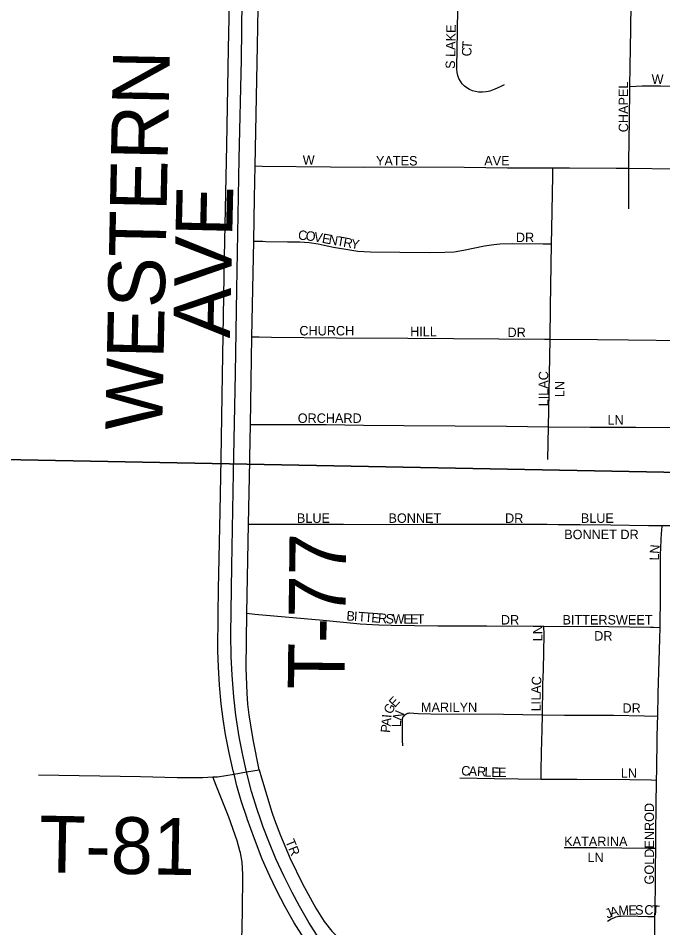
# Model space of a CAD drawing. Extents: x 0 to 68, y 0 to 52.9.
# Drawn here: x 42.193 to 43.045, y 38.666 to 39.867 of the extents above; entities that cross this region are included whole.
import ezdxf

# ---------------------------------------------------------------- set-up
doc = ezdxf.new("R2010")
doc.units = 0
for name, color, linetype in [('Default', 7, 'Continuous'), ('GM_X_Township_Road', 7, 'Continuous'), ('GM_X_Township_Road_Text', 7, 'Continuous'), ('GM_X_Township_Subdivision', 7, 'Continuous'), ('GM_X_Township_Subdivision_Text', 7, 'Continuous')]:
    doc.layers.add(name, color=color, linetype=linetype)

msp = doc.modelspace()

# ---------------------------------------------------------------- linework, layer by layer
at = {"layer": 'Default'}
for points in [[(43.183, 40.6024), (43.1833, 40.5874), (43.1609, 39.2654), (41.829, 39.2909), (41.8559, 40.6193)], [(41.829, 39.2909), (43.1609, 39.2654), (43.1327, 37.9528), (41.8088, 37.9756)]]:
    msp.add_lwpolyline(points, close=True, dxfattribs=at)
for points in [[(42.5132, 38.8091), (42.5087, 38.8222), (42.5015, 38.8458), (42.4947, 38.8716), (42.4898, 38.8937), (42.4852, 38.918), (42.4808, 38.9464), (42.4779, 38.9709), (42.4756, 38.9996), (42.4745, 39.0242), (42.4741, 39.053), (42.4755, 39.1433), (42.4776, 39.2665), (42.4801, 39.3978), (42.482, 39.5086), (42.4838, 39.6071), (42.4852, 39.681), (42.488, 39.8123), (42.4891, 39.8903), (42.4901, 39.9396), (42.4902, 39.9459)], [(42.5707, 38.6515), (42.5577, 38.6724), (42.5456, 38.6937), (42.5342, 38.7155), (42.5254, 38.7339), (42.5156, 38.7565), (42.5052, 38.7832), (42.4957, 38.8095), (42.4955, 38.8102), (42.4878, 38.8335), (42.4821, 38.8531), (42.4783, 38.8685), (42.4771, 38.873), (42.4718, 38.897), (42.4672, 38.9211), (42.4639, 38.9413), (42.4613, 38.9616), (42.4591, 38.9861), (42.4576, 39.0106), (42.457, 39.031), (42.4571, 39.0802), (42.4576, 39.113), (42.46, 39.2155), (42.4611, 39.2852), (42.4632, 39.3959), (42.4657, 39.5517), (42.4688, 39.6993), (42.471, 39.8265), (42.4731, 39.929)], [(42.8353, 39.7788), (42.8298, 39.7761), (42.8228, 39.773), (42.8163, 39.7707), (42.8139, 39.7701), (42.8114, 39.7698), (42.8066, 39.7694), (42.8014, 39.7694), (42.7974, 39.77), (42.7934, 39.7711), (42.7895, 39.7727), (42.786, 39.7748), (42.7827, 39.7773), (42.7797, 39.7803), (42.7773, 39.7836), (42.7753, 39.7873), (42.7739, 39.7912), (42.7731, 39.7952), (42.7727, 39.7994), (42.7725, 39.8035), (42.773, 39.8243), (42.774, 39.8782), (42.7742, 39.8885)], [(43.0012, 39.7766), (43.0015, 39.8031), (43.0026, 39.852), (43.0029, 39.8868)], [(42.9996, 39.6687), (42.9996, 39.6738), (43.0002, 39.7086), (43.0005, 39.7292), (43.0012, 39.7766)], [(43.0012, 39.7766), (43.0094, 39.7771), (43.0172, 39.7775), (43.0416, 39.7774), (43.0907, 39.7771), (43.1373, 39.7765), (43.1699, 39.7763), (43.174, 39.7763)], [(42.5063, 39.6718), (42.5156, 39.6717), (42.6058, 39.6708), (42.6509, 39.6703), (42.7042, 39.6705), (42.7822, 39.6701), (42.8396, 39.6694), (42.8994, 39.6693)], [(42.8978, 39.569), (42.8981, 39.5886), (42.8992, 39.6586), (42.8994, 39.6693)], [(42.8994, 39.6693), (42.9216, 39.6692), (42.9831, 39.6688), (42.9996, 39.6687)], [(42.9999, 39.615), (42.9999, 39.6268), (42.9996, 39.6687)], [(42.9996, 39.6687), (43.0611, 39.6682), (43.1185, 39.6677), (43.1553, 39.6676), (43.1722, 39.6676)], [(42.5044, 39.5727), (42.5162, 39.5723), (42.5203, 39.5721), (42.549, 39.5718), (42.5653, 39.5715), (42.5775, 39.5706), (42.5896, 39.569), (42.6015, 39.5664), (42.6095, 39.5646), (42.6338, 39.5604), (42.642, 39.5593), (42.6584, 39.5586), (42.7362, 39.5577), (42.7567, 39.5578), (42.7691, 39.5586), (42.7813, 39.5604), (42.8093, 39.5665), (42.8213, 39.5683), (42.8294, 39.569), (42.8457, 39.5696), (42.8867, 39.5691), (42.8978, 39.569)], [(42.8957, 39.4429), (42.8964, 39.4857), (42.8978, 39.569)], [(42.502, 39.446), (42.5114, 39.446), (42.5278, 39.4458), (42.6137, 39.4449), (42.708, 39.4445), (42.8885, 39.4429), (42.8957, 39.4429)], [(42.8937, 39.3275), (42.8941, 39.3499), (42.8957, 39.4429)], [(42.8957, 39.4429), (42.9582, 39.4425), (42.9992, 39.442), (43.073, 39.4414), (43.1087, 39.4409), (43.1311, 39.4409), (43.1542, 39.4408), (43.1682, 39.4408)], [(42.5, 39.3306), (42.5102, 39.3306), (42.6, 39.3302), (42.6493, 39.3296), (42.7027, 39.3292), (42.8383, 39.328), (42.8937, 39.3275)], [(42.8929, 39.284), (42.8937, 39.3275)], [(42.8937, 39.3275), (42.9489, 39.3269), (42.9929, 39.3269), (43.009, 39.3268), (43.0582, 39.3266), (43.107, 39.326), (43.1519, 39.3258), (43.156, 39.3257), (43.1661, 39.3254)], [(42.892, 39.1987), (42.9066, 39.1984), (42.9355, 39.1982), (42.9762, 39.1978), (43.0256, 39.1972), (43.0438, 39.1972)], [(43.041, 39.0624), (43.0417, 39.1049), (43.0417, 39.1585), (43.043, 39.1873), (43.0432, 39.1902), (43.0438, 39.1972)], [(43.0438, 39.1972), (43.0668, 39.1971), (43.1571, 39.197), (43.1639, 39.197)], [(42.8867, 38.9967), (42.887, 39.0067), (42.8879, 39.0529), (42.8876, 39.0641)], [(42.8876, 39.0641), (42.9733, 39.0635), (43.0283, 39.0629), (43.0324, 39.0628), (43.041, 39.0624)], [(43.038, 38.9454), (43.0387, 38.9752), (43.0393, 39.0039), (43.0408, 39.0475), (43.041, 39.0624)], [(42.8857, 38.9471), (42.8857, 38.9511), (42.8858, 38.9593), (42.8861, 38.9724), (42.8863, 38.9871), (42.8867, 38.9967)], [(42.7011, 38.9063), (42.701, 38.9134), (42.701, 38.9267), (42.7009, 38.9418), (42.7011, 38.9429), (42.7014, 38.9437), (42.7019, 38.9447), (42.7028, 38.9459), (42.7039, 38.947)], [(42.7039, 38.947), (42.7051, 38.9479), (42.706, 38.9484), (42.7068, 38.9488), (42.7077, 38.9491), (42.7087, 38.9494), (42.7102, 38.9495), (42.7216, 38.9489), (42.7384, 38.9484), (42.8344, 38.9477), (42.8598, 38.9474), (42.8857, 38.9471)], [(42.8838, 38.8622), (42.8839, 38.8725), (42.8844, 38.8972), (42.8851, 38.9274), (42.8857, 38.9471)], [(42.8857, 38.9471), (42.9146, 38.9468), (42.9797, 38.9464), (43.0204, 38.9458), (43.038, 38.9454)], [(43.0364, 38.8609), (43.0366, 38.8746), (43.0373, 38.9164), (43.0377, 38.9352), (43.038, 38.9454)], [(42.7765, 38.8637), (42.8222, 38.863), (42.8534, 38.8626), (42.8838, 38.8622)], [(42.8838, 38.8622), (42.8919, 38.8621), (42.9083, 38.8619), (42.9313, 38.8621), (43.0009, 38.8616), (43.0294, 38.861), (43.0364, 38.8609)], [(43.0354, 38.771), (43.0355, 38.7909), (43.0358, 38.827), (43.0364, 38.8609)], [(42.7557, 38.4627), (42.7433, 38.4754), (42.6779, 38.5434), (42.6528, 38.5706), (42.6366, 38.5893), (42.6213, 38.6086), (42.6043, 38.6318), (42.5904, 38.6522), (42.5772, 38.673), (42.5647, 38.6943), (42.5549, 38.7124), (42.544, 38.7345), (42.5337, 38.757), (42.5242, 38.7797), (42.5167, 38.7989), (42.5132, 38.8091)], [(42.5319, 38.8086), (42.5395, 38.7876), (42.5524, 38.7573), (42.5686, 38.7241), (42.5862, 38.6916), (42.5972, 38.6742), (42.6075, 38.6612), (42.6162, 38.6525), (42.6258, 38.6446), (42.6362, 38.6376), (42.6471, 38.6317), (42.6586, 38.627), (42.6705, 38.6236), (42.6868, 38.6209), (42.7115, 38.6192), (42.7771, 38.6179), (42.9001, 38.6174), (43.0343, 38.6162)], [(42.9142, 38.7719), (42.9315, 38.7719), (42.9569, 38.7718), (42.9905, 38.7715), (43.0258, 38.7711), (43.0354, 38.771)], [(43.0343, 38.6806), (43.0344, 38.69), (43.0349, 38.7261), (43.0352, 38.7442), (43.0354, 38.7704), (43.0354, 38.771)], [(42.9718, 38.6746), (42.9766, 38.6776), (42.9798, 38.6791), (42.9828, 38.6802), (42.9849, 38.6807), (42.9872, 38.6812), (42.9896, 38.6814), (42.9934, 38.6815), (43.0115, 38.681), (43.0247, 38.6807), (43.0343, 38.6806)], [(43.0343, 38.6162), (43.034, 38.6408), (43.0343, 38.6806)]]:
    msp.add_lwpolyline(points, dxfattribs=at)
at = {"layer": 'GM_X_Township_Road'}
for points in [[(42.5063, 39.6718), (42.5092, 39.8308), (42.5103, 39.8801), (42.5106, 39.8906)], [(42.5044, 39.5727), (42.5055, 39.6299), (42.5063, 39.6718)], [(42.502, 39.446), (42.5044, 39.5727)], [(42.5, 39.3306), (42.5009, 39.388), (42.502, 39.446)], [(42.4992, 39.2824), (42.4993, 39.287), (42.5, 39.3306)], [(42.4975, 39.199), (42.4992, 39.2824)], [(42.4951, 39.0811), (42.4975, 39.199)], [(42.5114, 38.8745), (42.5035, 38.9146), (42.5003, 38.9333), (42.4983, 38.9471), (42.4967, 38.9613), (42.4955, 38.9757), (42.4943, 39.0086), (42.4951, 39.0811)], [(42.22, 38.8678), (42.3545, 38.8658), (42.4033, 38.8645), (42.4318, 38.8641), (42.4369, 38.8644)], [(42.4501, 38.865), (42.4563, 38.8653), (42.4783, 38.8685)], [(42.4783, 38.8685), (42.4947, 38.8716)], [(42.4947, 38.8716), (42.5114, 38.8745)], [(42.5114, 38.8745), (42.5145, 38.8639), (42.5283, 38.8185), (42.5319, 38.8086)], [(42.4369, 38.8644), (42.4501, 38.865)], [(42.4772, 38.1139), (42.4785, 38.178), (42.4831, 38.3915), (42.4842, 38.4531), (42.4871, 38.5926), (42.4893, 38.6868), (42.4901, 38.7361), (42.489, 38.7527), (42.4868, 38.7649), (42.4861, 38.7674), (42.4824, 38.7808), (42.4715, 38.8119), (42.4546, 38.8538), (42.4501, 38.865)]]:
    msp.add_lwpolyline(points, dxfattribs=at)
at = {"layer": 'GM_X_Township_Subdivision'}
for points in [[(42.4975, 39.199), (42.52, 39.1987), (42.5507, 39.1988), (42.6227, 39.1989), (42.6799, 39.1985), (42.7371, 39.1988), (42.8434, 39.1986), (42.892, 39.1987)], [(42.4951, 39.0811), (42.5057, 39.0801), (42.5958, 39.072), (42.645, 39.0673), (42.6695, 39.0658), (42.6859, 39.0654), (42.7476, 39.0646), (42.812, 39.0644), (42.8876, 39.0641)]]:
    msp.add_lwpolyline(points, dxfattribs=at)

# ---------------------------------------------------------------- texts
at = {"layer": 'Default'}
for s, rotation, p in [('S LAKE', 88.8315, (42.7701, 39.7999)), ('T', 85.6516, (42.7919, 39.826)), ('C', 88.2753, (42.7917, 39.8163)), ('W', 0, (43.0299, 39.7802)), ('CHAPEL', 90, (42.9989, 39.7163)), ('W', 0, (42.569, 39.6735)), ('YATES', 0, (42.6658, 39.6724)), ('AVE', 0, (42.8088, 39.6724)), ('C', 355.7466, (42.5626, 39.5745)), ('O', 352.791, (42.5723, 39.5738)), ('V', 349.5603, (42.583, 39.5725)), ('E', 349.5583, (42.5938, 39.5705)), ('N', 349.5793, (42.6025, 39.5689)), ('T', 349.5583, (42.6133, 39.5669)), ('R', 349.5727, (42.6219, 39.5653)), ('Y', 350.6939, (42.6319, 39.5634)), ('DR', 0, (42.8506, 39.5712)), ('CHURCH', 0, (42.5646, 39.448)), ('HILL', 0, (42.7109, 39.4469)), ('DR', 0, (42.8396, 39.4458)), ('LILAC', 90, (42.8933, 39.3544)), ('LN', 90, (42.9146, 39.3665)), ('ORCHARD', 0, (42.5624, 39.3325)), ('LN', 0, (42.9716, 39.3303)), ('BLUE', 0, (42.9364, 39.2005)), ('BONNET DR', 0, (42.9144, 39.179)), ('N', 85.7773, (43.0398, 39.1594)), ('L', 88.8526, (43.0396, 39.1508)), ('BITTERSWEET', 0, (42.9122, 39.0663)), ('LN', 90, (42.8857, 39.0442)), ('DR', 0, (42.954, 39.0451)), ('C', 85.795, (42.8836, 38.9856)), ('A', 89.4098, (42.8835, 38.9748)), ('E', 47.1068, (42.6906, 38.956)), ('MARILYN', 0, (42.7252, 38.9508)), ('L', 89.9457, (42.8835, 38.9661)), ('I', 89.9126, (42.8835, 38.9606)), ('G', 64.2463, (42.6863, 38.9469)), ('N', 66.7899, (42.6988, 38.9384)), ('L', 89.9453, (42.8834, 38.9518)), ('DR', 0, (42.9914, 38.9497)), ('A', 84.7462, (42.6851, 38.9316)), ('I', 84.7796, (42.6861, 38.9426)), ('L', 89.5355, (42.699, 38.9308)), ('P', 84.7734, (42.6843, 38.9229)), ('C', 357.157, (42.7781, 38.8672)), ('A', 357.1556, (42.788, 38.8667)), ('R', 357.1645, (42.799, 38.8662)), ('L', 357.1581, (42.8089, 38.8657)), ('E', 358.663, (42.818, 38.8652)), ('E', 359.9073, (42.8271, 38.865)), ('LN', 0, (42.9892, 38.8639)), ('GOLDENROD', 90, (43.033, 38.723)), ('TR', 292.3821, (42.5458, 38.78)), ('KATARINA', 0, (42.9144, 38.7737)), ('LN', 0, (42.9452, 38.7525)), ('J', 23.0436, (42.9717, 38.6778)), ('A', 14.2907, (42.9763, 38.6798)), ('M', 1.9674, (42.9862, 38.6824)), ('E', 1.4212, (42.9994, 38.6829)), ('S', 1.4509, (43.0082, 38.6831)), ('C', 358.8101, (43.0201, 38.6834)), ('T', 356.7747, (43.0299, 38.6832))]:
    msp.add_text(s, height=0.0125, rotation=rotation, dxfattribs=at).set_placement(p)
at = {"layer": 'GM_X_Township_Road_Text'}
for s, rotation, p in [('WESTERN', 88.8337, (42.3833, 39.3223)), ('AVE', 88.6532, (42.4727, 39.4441)), ('T-77', 89.3265, (42.6242, 38.9801)), ('T-81', 358.9397, (42.2201, 38.7391))]:
    msp.add_text(s, height=0.075, rotation=rotation, dxfattribs=at).set_placement(p)
at = {"layer": 'GM_X_Township_Subdivision_Text'}
for s, rotation, p in [('BLUE', 0, (42.5613, 39.2005)), ('BONNET', 0, (42.6823, 39.2005)), ('DR', 0, (42.8363, 39.2005)), ('B', 355.795, (42.6264, 39.0718)), ('I', 355.7991, (42.6363, 39.0711)), ('T', 355.7878, (42.6417, 39.0707)), ('T', 355.7843, (42.6505, 39.07)), ('E', 355.7843, (42.6593, 39.0694)), ('R', 355.7949, (42.6681, 39.0688)), ('S', 356.9242, (42.6782, 39.068)), ('W', 359.6583, (42.6876, 39.0675)), ('E', 359.9956, (42.702, 39.0674)), ('E', 359.9956, (42.7108, 39.0674)), ('T', 359.9956, (42.7196, 39.0674)), ('DR', 0, (42.8308, 39.0663))]:
    msp.add_text(s, height=0.0125, rotation=rotation, dxfattribs=at).set_placement(p)

doc.saveas('drawing.dxf')
